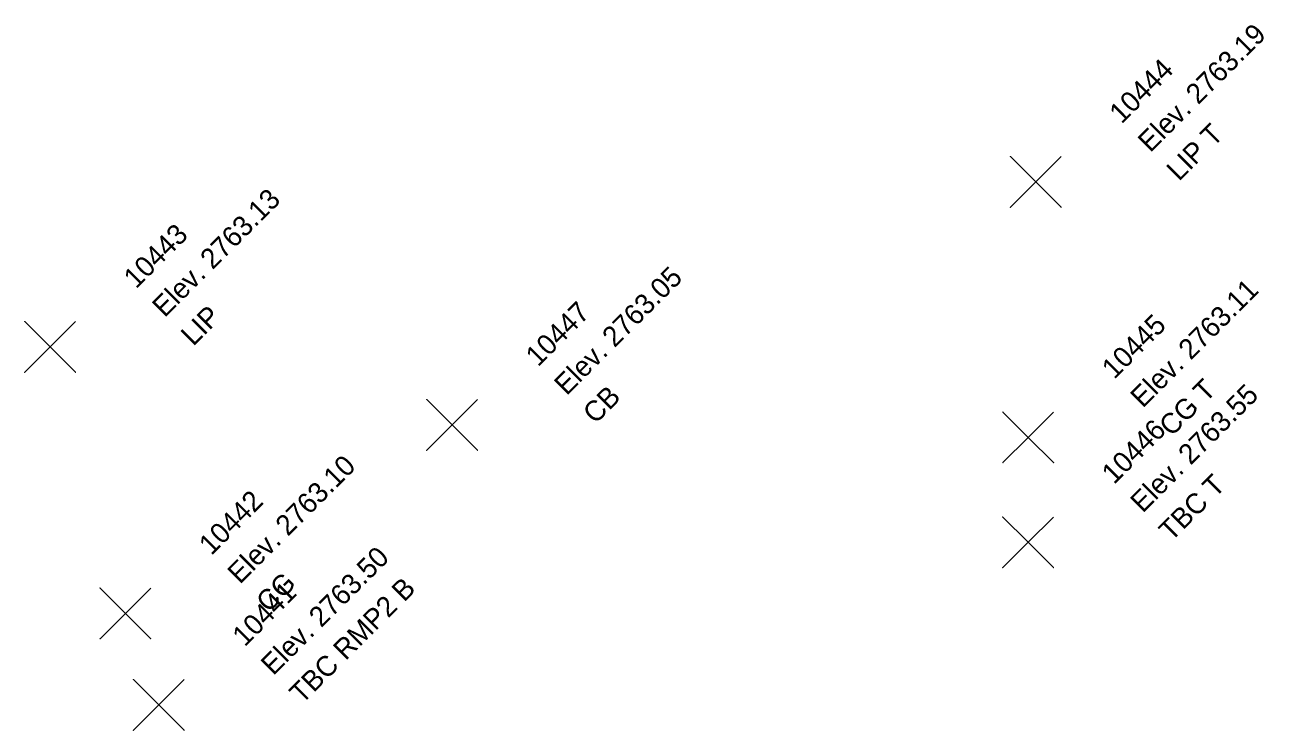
# Model space of a CAD drawing. Extents: x 2493999 to 2503109, y 700767 to 706646.
# Drawn here: x 2502627.39 to 2502634.73, y 701310.84 to 701315.01 of the extents above; entities that cross this region are included whole.
import ezdxf

# ---------------------------------------------------------------- set-up
doc = ezdxf.new("R2010")
doc.units = 0
doc.layers.add('ALG_CL_BLUE_Horiz', color=7, linetype='Continuous')
doc.layers.add('DES_SURFACE_Existing-Ground', color=7, linetype='Continuous')

msp = doc.modelspace()

# ---------------------------------------------------------------- linework, layer by layer
at = {"layer": 'ALG_CL_BLUE_Horiz'}
for points in [[(2502633.377, 701314.084), (2502633.227, 701314.234), (2502633.377, 701314.084), (2502633.227, 701313.934), (2502633.377, 701314.084), (2502633.527, 701313.934), (2502633.377, 701314.084), (2502633.527, 701314.234)], [(2502627.537, 701313.107), (2502627.387, 701313.257), (2502627.537, 701313.107), (2502627.387, 701312.957), (2502627.537, 701313.107), (2502627.687, 701312.957), (2502627.537, 701313.107), (2502627.687, 701313.257)], [(2502629.919, 701312.645), (2502629.769, 701312.795), (2502629.919, 701312.645), (2502629.769, 701312.495), (2502629.919, 701312.645), (2502630.069, 701312.495), (2502629.919, 701312.645), (2502630.069, 701312.795)], [(2502633.333, 701312.571), (2502633.183, 701312.721), (2502633.333, 701312.571), (2502633.183, 701312.421), (2502633.333, 701312.571), (2502633.483, 701312.421), (2502633.333, 701312.571), (2502633.483, 701312.721)], [(2502633.332, 701311.949), (2502633.182, 701312.099), (2502633.332, 701311.949), (2502633.182, 701311.799), (2502633.332, 701311.949), (2502633.482, 701311.799), (2502633.332, 701311.949), (2502633.482, 701312.099)], [(2502627.983, 701311.528), (2502627.833, 701311.678), (2502627.983, 701311.528), (2502627.833, 701311.378), (2502627.983, 701311.528), (2502628.133, 701311.378), (2502627.983, 701311.528), (2502628.133, 701311.678)], [(2502628.181, 701310.986), (2502628.031, 701311.136), (2502628.181, 701310.986), (2502628.031, 701310.836), (2502628.181, 701310.986), (2502628.331, 701310.836), (2502628.181, 701310.986), (2502628.331, 701311.136)]]:
    msp.add_lwpolyline(points, dxfattribs=at)

# ---------------------------------------------------------------- texts
at = {"layer": 'DES_SURFACE_Existing-Ground'}
for s, p in [('Elev. 2763.19', (2502634.0558, 701314.2537)), ('10444', (2502633.8861, 701314.4234)), ('LIP T', (2502634.2255, 701314.084)), ('Elev. 2763.13', (2502628.2158, 701313.2767)), ('10443', (2502628.0461, 701313.4464)), ('Elev. 2763.05', (2502630.5978, 701312.8147)), ('Elev. 2763.11', (2502634.0118, 701312.7407)), ('LIP', (2502628.3855, 701313.107)), ('10447', (2502630.4281, 701312.9844)), ('10445', (2502633.8421, 701312.9104)), ('CG T', (2502634.1815, 701312.571)), ('CB', (2502630.7675, 701312.645)), ('Elev. 2763.55', (2502634.0108, 701312.1187)), ('10446', (2502633.8411, 701312.2884)), ('Elev. 2763.10', (2502628.6618, 701311.6977)), ('TBC T', (2502634.1805, 701311.949)), ('10442', (2502628.4921, 701311.8674)), ('Elev. 2763.50', (2502628.8598, 701311.1557)), ('CG', (2502628.8315, 701311.528)), ('TBC RMP2 B', (2502629.0295, 701310.986)), ('10441', (2502628.6901, 701311.3254))]:
    msp.add_text(s, height=0.12, rotation=45, dxfattribs=at).set_placement(p)

doc.saveas('drawing.dxf')
